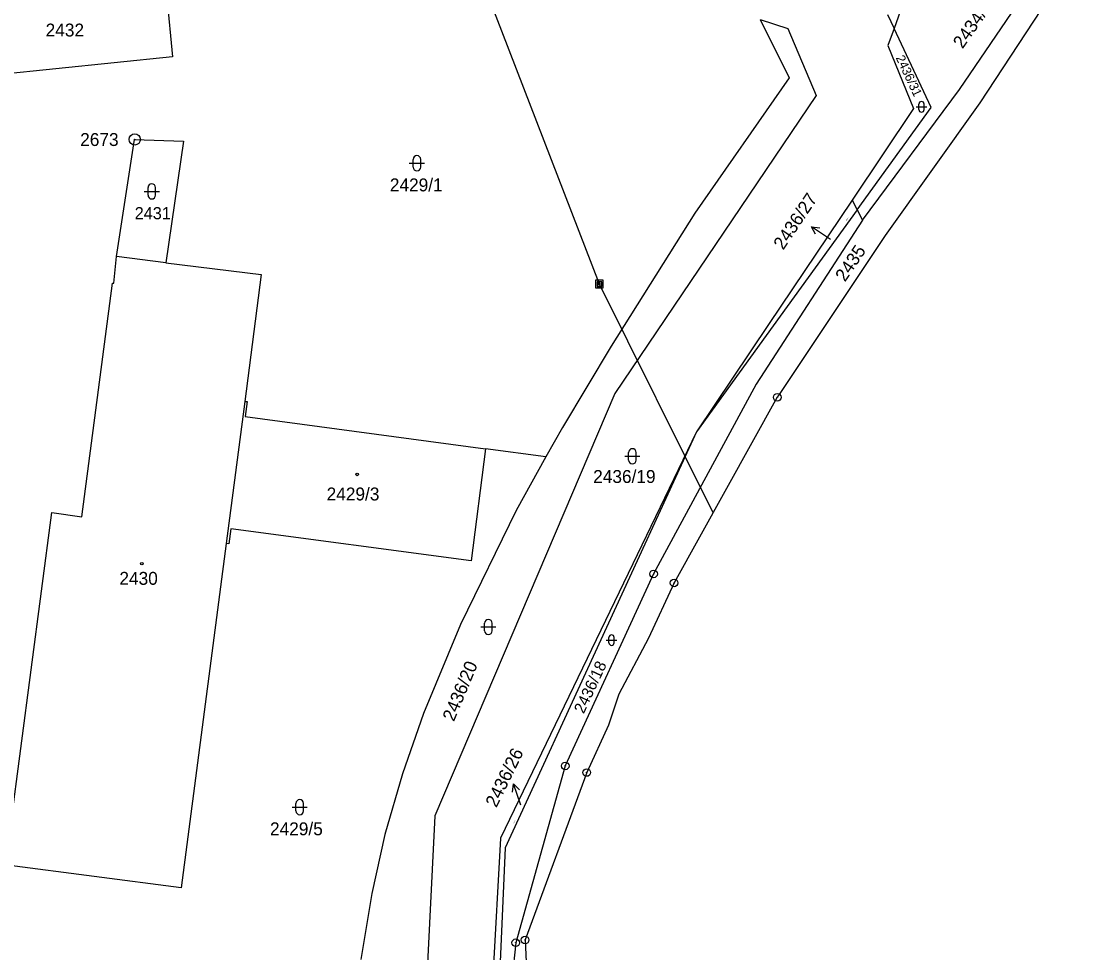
# Model space of a CAD drawing. Extents: x -822293 to -820259, y -1071573 to -1068794.
# Drawn here: x -820475.7 to -820337.2, y -1069490.3 to -1069367.7 of the extents above; entities that cross this region are included whole.
import ezdxf

# ---------------------------------------------------------------- set-up
doc = ezdxf.new("R2010")
doc.units = 0
for name, color, linetype in [('Vrstva 1', 7, 'Continuous'), ('Vrstva 12', 7, 'Continuous'), ('Vrstva 13', 7, 'Continuous'), ('Vrstva 16', 7, 'Continuous'), ('Vrstva 17', 7, 'Continuous'), ('Vrstva 18', 7, 'Continuous'), ('Vrstva 19', 7, 'Continuous'), ('Vrstva 24', 7, 'Continuous'), ('Vrstva 25', 7, 'Continuous'), ('Vrstva 26', 7, 'Continuous')]:
    doc.layers.add(name, color=color, linetype=linetype)

msp = doc.modelspace()

# ---------------------------------------------------------------- linework, layer by layer
at = {"layer": 'Vrstva 1'}
for p, q in [((-820352.14, -1069376.7), (-820339.56, -1069358.23)), ((-820456.8, -1069361.32), (-820455.77, -1069372.39)), ((-820361.62, -1069366.83), (-820360.76, -1069368.66)), ((-820359.64, -1069365.55), (-820360.76, -1069368.66)), ((-820378.38, -1069367.48), (-820374.58, -1069375.18)), ((-820378.38, -1069367.48), (-820374.77, -1069368.68)), ((-820374.77, -1069368.68), (-820371.02, -1069377.51)), ((-820360.76, -1069368.66), (-820361.58, -1069370.91)), ((-820355.87, -1069379.09), (-820360.76, -1069368.66)), ((-820361.58, -1069370.91), (-820358.19, -1069379.19)), ((-820455.77, -1069372.39), (-820482.69, -1069375.18)), ((-820374.58, -1069375.18), (-820386.98, -1069392.96)), ((-820371.02, -1069377.51), (-820397.52, -1069416.69)), ((-820364.9, -1069393.92), (-820352.14, -1069376.7)), ((-820358.19, -1069379.19), (-820366.29, -1069391.25)), ((-820365.62, -1069392.55), (-820355.87, -1069379.09)), ((-820463.13, -1069398.7), (-820460.76, -1069383.29)), ((-820460.76, -1069383.29), (-820454.3, -1069383.51)), ((-820454.3, -1069383.51), (-820456.65, -1069399.5)), ((-820366.29, -1069391.25), (-820377.3, -1069407.64)), ((-820366.29, -1069391.25), (-820365.62, -1069392.55)), ((-820386.98, -1069392.96), (-820398.03, -1069410.48)), ((-820365.62, -1069392.55), (-820377.6, -1069409.09)), ((-820365.62, -1069392.55), (-820364.9, -1069393.92)), ((-820364.9, -1069393.92), (-820378.93, -1069415.49)), ((-820463.5, -1069402.19), (-820463.13, -1069398.7)), ((-820456.65, -1069399.5), (-820463.13, -1069398.7)), ((-820456.65, -1069399.5), (-820444.07, -1069401.06)), ((-820444.07, -1069401.06), (-820446.26, -1069417.77)), ((-820467.71, -1069432.95), (-820463.65, -1069402.17)), ((-820463.65, -1069402.17), (-820463.5, -1069402.19)), ((-820377.3, -1069407.64), (-820386.77, -1069421.75)), ((-820377.6, -1069409.09), (-820386.77, -1069421.75)), ((-820398.03, -1069410.48), (-820404.43, -1069421.16)), ((-820397.52, -1069416.69), (-820421.21, -1069472.29)), ((-820378.93, -1069415.49), (-820392.43, -1069440.45)), ((-820446.26, -1069417.77), (-820448.7, -1069436.43)), ((-820446.26, -1069417.77), (-820445.94, -1069417.78)), ((-820445.94, -1069417.78), (-820446.18, -1069419.75)), ((-820446.18, -1069419.75), (-820414.55, -1069423.98)), ((-820386.77, -1069421.75), (-820412.6, -1069475.2)), ((-820386.77, -1069421.75), (-820411.98, -1069476.49)), ((-820404.43, -1069421.16), (-820406.6, -1069425.04)), ((-820414.55, -1069423.98), (-820416.43, -1069438.73)), ((-820406.6, -1069425.04), (-820414.55, -1069423.98)), ((-820406.6, -1069425.04), (-820410.53, -1069432.1)), ((-820477.11, -1069473.76), (-820471.65, -1069432.38)), ((-820471.65, -1069432.38), (-820467.71, -1069432.95)), ((-820410.53, -1069432.1), (-820417.83, -1069447.1)), ((-820448.1, -1069434.51), (-820448.35, -1069436.47)), ((-820416.43, -1069438.73), (-820448.1, -1069434.51)), ((-820448.7, -1069436.43), (-820454.63, -1069481.77)), ((-820448.35, -1069436.47), (-820448.7, -1069436.43)), ((-820392.43, -1069440.45), (-820404.06, -1069465.71)), ((-820417.83, -1069447.1), (-820422.73, -1069458.8)), ((-820422.73, -1069458.8), (-820425.48, -1069466.76)), ((-820404.06, -1069465.71), (-820410.58, -1069488.98)), ((-820425.48, -1069466.76), (-820427.8, -1069474.74)), ((-820421.21, -1069472.29), (-820422.97, -1069507.22)), ((-820427.8, -1069474.74), (-820429.54, -1069482.5)), ((-820412.6, -1069475.2), (-820414.37, -1069507.12)), ((-820411.98, -1069476.49), (-820413.29, -1069507.11)), ((-820454.63, -1069481.77), (-820477.55, -1069478.76)), ((-820429.54, -1069482.5), (-820430.99, -1069491.17)), ((-820410.58, -1069488.98), (-820412.39, -1069506.82))]:
    msp.add_line(p, q, dxfattribs=at)
at = {"layer": 'Vrstva 12'}
for p, q in [((-820399.56, -1069402.31), (-820428.56, -1069327.25)), ((-820384.6, -1069432.42), (-820399.56, -1069402.31))]:
    msp.add_line(p, q, dxfattribs=at)
at = {"layer": 'Vrstva 13'}
for p, q in [((-820337.21, -1069359.68), (-820349.46, -1069378.44)), ((-820349.46, -1069378.44), (-820361.93, -1069395.91)), ((-820361.93, -1069395.91), (-820375.89, -1069416.82)), ((-820376.14, -1069417.21), (-820389.73, -1069441.64)), ((-820375.89, -1069416.82), (-820376.14, -1069417.21)), ((-820389.73, -1069441.64), (-820393.08, -1069448.9)), ((-820393.08, -1069448.9), (-820397.02, -1069456.26)), ((-820397.02, -1069456.26), (-820398.35, -1069460.33)), ((-820398.35, -1069460.33), (-820401.23, -1069466.58)), ((-820401.23, -1069466.58), (-820409.34, -1069488.62)), ((-820409.34, -1069488.62), (-820408.55, -1069507.05))]:
    msp.add_line(p, q, dxfattribs=at)
at = {"layer": 'Vrstva 16'}
for p, q in [((-820369.15, -1069396.46), (-820371.64, -1069394.786)), ((-820409.92, -1069470.9), (-820410.862, -1069468.052))]:
    msp.add_line(p, q, dxfattribs=at)
for points in [[(-820371.089, -1069395.759), (-820371.64, -1069394.786), (-820370.531, -1069394.929)], [(-820411.022, -1069469.158), (-820410.862, -1069468.052), (-820410.073, -1069468.844)]]:
    msp.add_lwpolyline(points, dxfattribs=at)
at = {"layer": 'Vrstva 24'}
for centre, radius in [((-820460.74, -1069383.27), 0.75), ((-820460.74, -1069383.27), 0.0327), ((-820376.14, -1069417.21), 0.5), ((-820376.14, -1069417.21), 0.0327), ((-820392.43, -1069440.45), 0.5), ((-820392.43, -1069440.45), 0.0327), ((-820389.73, -1069441.64), 0.5), ((-820389.73, -1069441.64), 0.0327), ((-820404.06, -1069465.71), 0.5), ((-820404.06, -1069465.71), 0.0327), ((-820401.23, -1069466.58), 0.5), ((-820401.23, -1069466.58), 0.0327), ((-820410.58, -1069488.98), 0.5), ((-820409.34, -1069488.62), 0.5), ((-820409.34, -1069488.62), 0.0327), ((-820410.58, -1069488.98), 0.0327)]:
    msp.add_circle(centre, radius, dxfattribs=at)
at = {"layer": 'Vrstva 25'}
for p, q in [((-820357.85, -1069378.99), (-820356.45, -1069378.99)), ((-820357.5, -1069379.34), (-820357.5, -1069378.64)), ((-820356.8, -1069379.34), (-820356.8, -1069378.64)), ((-820424.09, -1069386.91), (-820424.09, -1069385.91)), ((-820423.09, -1069386.91), (-820423.09, -1069385.91)), ((-820424.59, -1069386.41), (-820422.59, -1069386.41)), ((-820459.49, -1069390.11), (-820457.49, -1069390.11)), ((-820458.99, -1069390.61), (-820458.99, -1069389.61)), ((-820457.99, -1069390.61), (-820457.99, -1069389.61)), ((-820396.22, -1069424.97), (-820394.22, -1069424.97)), ((-820395.72, -1069425.47), (-820395.72, -1069424.47)), ((-820394.72, -1069425.47), (-820394.72, -1069424.47)), ((-820414.68, -1069447.93), (-820414.68, -1069446.93)), ((-820413.68, -1069447.93), (-820413.68, -1069446.93)), ((-820415.18, -1069447.43), (-820413.18, -1069447.43)), ((-820398.66, -1069449.16), (-820397.26, -1069449.16)), ((-820398.31, -1069449.51), (-820398.31, -1069448.81)), ((-820397.61, -1069449.51), (-820397.61, -1069448.81)), ((-820439.52, -1069471.64), (-820439.52, -1069470.64)), ((-820438.52, -1069471.64), (-820438.52, -1069470.64)), ((-820440.02, -1069471.14), (-820438.02, -1069471.14))]:
    msp.add_line(p, q, dxfattribs=at)
for centre in [(-820431.46, -1069427.35), (-820459.79, -1069439.1)]:
    msp.add_circle(centre, 0.175, dxfattribs=at)
for centre, radius, start, end in [((-820357.15, -1069378.64), 0.35, 0, 180), ((-820357.15, -1069379.34), 0.35, 180, 0), ((-820423.59, -1069385.91), 0.5, 0, 180), ((-820423.59, -1069386.91), 0.5, 180, 0), ((-820458.49, -1069389.61), 0.5, 0, 180), ((-820458.49, -1069390.61), 0.5, 180, 0), ((-820395.22, -1069424.47), 0.5, 0, 180), ((-820395.22, -1069425.47), 0.5, 180, 0), ((-820414.18, -1069446.93), 0.5, 0, 180), ((-820414.18, -1069447.93), 0.5, 180, 0), ((-820397.96, -1069448.81), 0.35, 0, 180), ((-820397.96, -1069449.51), 0.35, 180, 0), ((-820439.02, -1069470.64), 0.5, 0, 180), ((-820439.02, -1069471.64), 0.5, 180, 0)]:
    msp.add_arc(centre, radius, start, end, dxfattribs=at)
at = {"layer": 'Vrstva 26'}
for points in [[(-820399.06, -1069401.81), (-820400.06, -1069401.81), (-820400.06, -1069402.81), (-820399.06, -1069402.81)], [(-820399.26, -1069402.01), (-820399.86, -1069402.01), (-820399.86, -1069402.61), (-820399.26, -1069402.61)], [(-820399.66, -1069402.41), (-820399.46, -1069402.41), (-820399.46, -1069402.21), (-820399.66, -1069402.21)]]:
    msp.add_lwpolyline(points, close=True, dxfattribs=at)

# ---------------------------------------------------------------- texts
at = {"layer": 'Vrstva 16'}
for s, rotation, p in [('2434/3', 55.06128, (-820351.746, -1069371.433)), ('2436/27', 56.09259, (-820375.36, -1069397.91)), ('2435', 55.97802, (-820367.224, -1069402.108)), ('2436/26', 63.88479, (-820413.124, -1069471.297))]:
    msp.add_text(s, height=1.7, rotation=rotation, dxfattribs=at).set_placement(p)
at = {"layer": 'Vrstva 17'}
msp.add_text('2673', height=1.7, dxfattribs=at).set_placement((-820467.919, -1069384.14))
at = {"layer": 'Vrstva 18'}
for s, height, rotation, p in [('2436/31', 1.2, 295.11819, (-820360.572, -1069372.521)), ('2436/27', 0.1, 54.48825, (-820367.013, -1069393.952)), ('2436/20', 1.7, 67.2759, (-820418.718, -1069459.961)), ('2436/18', 1.5, 64.97343, (-820401.625, -1069458.937)), ('2436/26', 0.1, 64.9161, (-820410.82, -1069473.342))]:
    msp.add_text(s, height=height, rotation=rotation, dxfattribs=at).set_placement(p)
for s, height, p in [('2429/1', 1.7, (-820427.15, -1069390.11)), ('2431', 1.6, (-820460.743, -1069393.78)), ('2436/19', 1.7, (-820400.38, -1069428.48)), ('2429/5', 1.7, (-820442.929, -1069474.84))]:
    msp.add_text(s, height=height, dxfattribs=at).set_placement(p)
at = {"layer": 'Vrstva 19'}
for s, p in [('2432', (-820472.47, -1069369.73)), ('2429/3', (-820435.474, -1069430.78)), ('2430', (-820462.758, -1069441.88))]:
    msp.add_text(s, height=1.7, dxfattribs=at).set_placement(p)

doc.saveas('drawing.dxf')
